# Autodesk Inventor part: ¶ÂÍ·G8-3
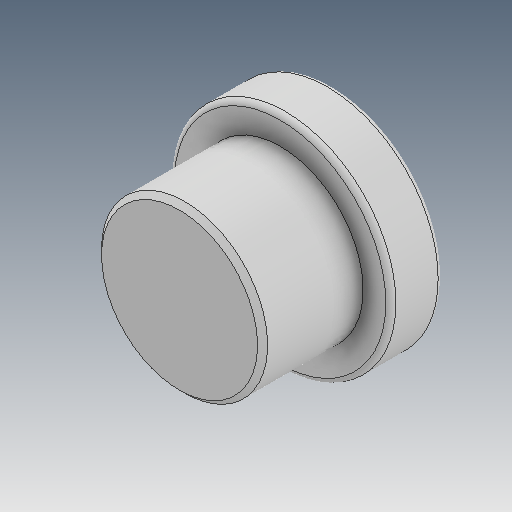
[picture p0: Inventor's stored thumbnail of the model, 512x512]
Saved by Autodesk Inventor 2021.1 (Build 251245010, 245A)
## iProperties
Created: 2018-07
Part Number: ¶ÂÍ·G8-3
Material: Ogólny
Document SubType Name: Modeling
Designer: user
Density: 1 g/cm^3
Appearance: Domyślna
Author: user
Revision Number: ÈÎºÎ
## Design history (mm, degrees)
feature "µ¹½Ç2"
node "Bryła1"
